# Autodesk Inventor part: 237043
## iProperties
Created: 2006-01
Part Number: 237043
Material: FSt
Document SubType Name: Modeling
Designer: I.Baliuc
Manufacturer: Standard
Standards Organization: Custom
Description: Ringfeder
Density: 7.85 g/cm^3
Abmessung: N7
Author: T.Messerschmitt
Revision Number: 237043
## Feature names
1. Basis1
